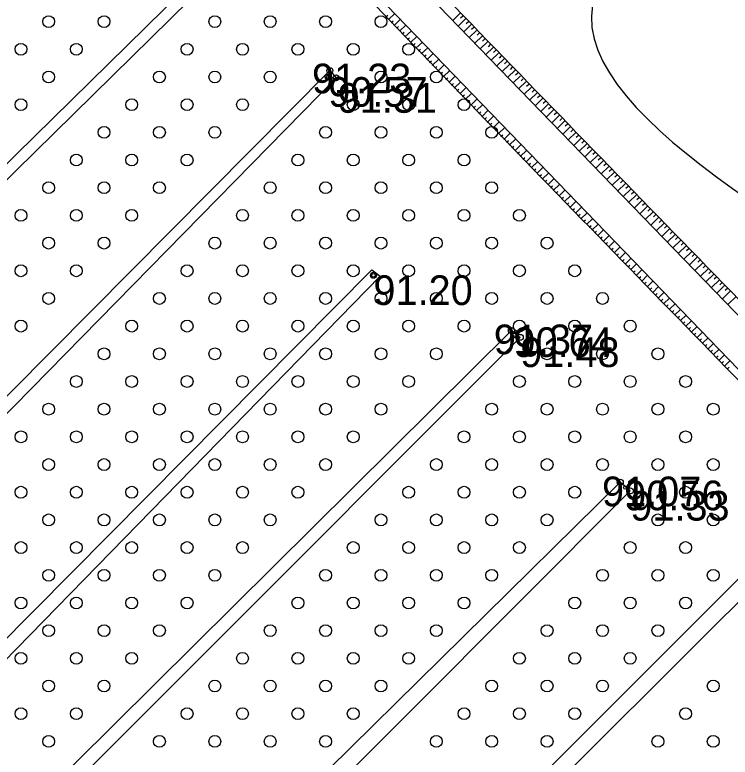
# Model space of a CAD drawing. Extents: x 316000 to 728450, y 314368 to 726000.
# Drawn here: x 725766.2 to 725856.6, y 315456.5 to 315550.4 of the extents above; entities that cross this region are included whole.
import ezdxf

# ---------------------------------------------------------------- set-up
doc = ezdxf.new("R2010")
doc.units = 0
for name, color, linetype in [('HIDG_ELEM_####_####_#', 7, 'Continuous'), ('HIDG_GRAV_####_####_#', 7, 'Continuous'), ('RELJ_AATZ_####_TKST_#', 7, 'Continuous'), ('RELJ_ELEM_####_####_#', 7, 'Continuous'), ('RELJ_HORZ_PAMT_####_#', 7, 'Continuous'), ('RELJ_NOGA_####_####_#', 7, 'Continuous'), ('TERT_ELEM_####_####_#', 7, 'Continuous')]:
    doc.layers.add(name, color=color, linetype=linetype)

msp = doc.modelspace()

# ---------------------------------------------------------------- linework, layer by layer
at = {"layer": 'HIDG_ELEM_####_####_#'}
for centre in [(725805.842, 315542.486), (725811.549, 315517.418), (725829.423, 315509.915), (725843.383, 315490.595)]:
    msp.add_circle(centre, 0.225, dxfattribs=at)
at = {"layer": 'HIDG_GRAV_####_####_#'}
for points in [[(726259.175, 315086.515), (726260.768, 315088.859), (726179.005, 315175.766), (726127.859, 315229.056), (726063.055, 315296.073), (725998.338, 315364.317), (725936.648, 315430.32), (725875.345, 315494.083), (725809.436, 315562.192), (725743.944, 315631.872)], [(725741.161, 315628.109), (725806.062, 315558.993), (725870.895, 315491.871), (725934.12, 315427.077), (725995.775, 315361.632), (726059.846, 315293.396), (726126.03, 315226.728), (726194.491, 315154.86), (726259.175, 315086.515)], [(725789.821, 315555.772), (725790.78, 315554.709), (725668.395, 315434.39), (725667.719, 315435.797), (725789.821, 315555.772)], [(725806.049, 315543.31), (725806.834, 315542.392), (725671.92, 315404.847), (725670.303, 315406.432), (725806.049, 315543.31)], [(725811.357, 315518.129), (725812.41, 315517.334), (725689.872, 315391.756), (725687.944, 315393.638), (725811.357, 315518.129)], [(725828.984, 315510.455), (725830.109, 315509.579), (725700.226, 315379.564), (725698.486, 315381.013), (725828.984, 315510.455)], [(725715.114, 315365.54), (725717.512, 315363.33), (725844.018, 315490.166), (725842.748, 315491.255), (725715.114, 315365.54)], [(725860.372, 315481.728), (725862.243, 315480.659), (725694.367, 315313.346), (725693.183, 315314.534), (725860.372, 315481.728)]]:
    msp.add_lwpolyline(points, dxfattribs=at)
at = {"layer": 'RELJ_ELEM_####_####_#'}
for centre in [(725806.049, 315543.31), (725805.842, 315542.486), (725806.834, 315542.392), (725811.549, 315517.418), (725828.984, 315510.455), (725829.423, 315509.915), (725830.109, 315509.579), (725842.748, 315491.255), (725844.018, 315490.166)]:
    msp.add_circle(centre, 0.375, dxfattribs=at)
at = {"layer": 'RELJ_HORZ_PAMT_####_#'}
msp.add_spline([(726116.344, 315699.088), (726105.94, 315702.687), (726040.128, 315715), (725990.823, 315710.424), (725942.032, 315708.248), (725920.28, 315706.773), (725880.366, 315714.514), (725859.054, 315708.681), (725859.054, 315672.662), (725851.263, 315613.969), (725853.471, 315568.895), (725840.997, 315555.788), (725885.558, 315509.629), (725935.943, 315461.491), (725983.423, 315406.25), (726032.861, 315360.511), (726082.852, 315311.191), (726122.235, 315248.757), (726137.049, 315229.286), (726180.187, 315183.1), (726194.517, 315168.27), (726211.91, 315146.926), (726212.513, 315143.157)], degree=3, dxfattribs=at)
at = {"layer": 'RELJ_NOGA_####_####_#'}
for p, q in [((725813.115, 315550.109), (725813.354, 315550.336)), ((725813.46, 315549.747), (725814.258, 315550.507)), ((725814.149, 315549.023), (725814.953, 315549.789)), ((725822.506, 315550.56), (725821.566, 315549.657)), ((725823.199, 315549.839), (725822.262, 315548.938)), ((725822.852, 315550.199), (725822.571, 315549.929)), ((725813.804, 315549.385), (725814.045, 315549.614)), ((725814.494, 315548.661), (725814.736, 315548.891)), ((725814.839, 315548.299), (725815.647, 315549.069)), ((725823.892, 315549.118), (725822.958, 315548.219)), ((725823.545, 315549.479), (725823.265, 315549.209)), ((725815.184, 315547.937), (725815.427, 315548.169)), ((725815.53, 315547.575), (725816.342, 315548.351)), ((725824.586, 315548.398), (725823.654, 315547.5)), ((725824.239, 315548.758), (725823.959, 315548.488)), ((725824.933, 315548.038), (725824.653, 315547.769)), ((725815.875, 315547.214), (725816.119, 315547.447)), ((725816.22, 315546.852), (725817.036, 315547.632)), ((725816.912, 315546.13), (725817.73, 315546.913)), ((725825.279, 315547.678), (725824.349, 315546.781)), ((725825.974, 315546.958), (725825.045, 315546.062)), ((725825.627, 315547.318), (725825.348, 315547.049)), ((725816.566, 315546.491), (725816.811, 315546.725)), ((725817.257, 315545.768), (725817.503, 315546.004)), ((725817.603, 315545.407), (725818.424, 315546.194)), ((725826.668, 315546.238), (725825.741, 315545.343)), ((725826.321, 315546.598), (725826.042, 315546.329)), ((725817.949, 315545.046), (725818.196, 315545.283)), ((725818.295, 315544.685), (725819.119, 315545.475)), ((725827.363, 315545.519), (725826.436, 315544.624)), ((725827.015, 315545.878), (725826.737, 315545.61)), ((725827.71, 315545.159), (725827.432, 315544.891)), ((725818.641, 315544.324), (725818.888, 315544.562)), ((725818.987, 315543.963), (725819.813, 315544.756)), ((725828.058, 315544.8), (725827.132, 315543.905)), ((725828.405, 315544.44), (725828.127, 315544.172)), ((725819.333, 315543.603), (725819.581, 315543.841)), ((725819.679, 315543.242), (725820.508, 315544.037)), ((725820.372, 315542.521), (725821.202, 315543.318)), ((725828.753, 315544.081), (725827.828, 315543.186)), ((725829.448, 315543.362), (725828.523, 315542.467)), ((725829.1, 315543.722), (725828.823, 315543.453)), ((725820.026, 315542.881), (725820.274, 315543.12)), ((725820.719, 315542.16), (725820.968, 315542.4)), ((725821.065, 315541.8), (725821.897, 315542.599)), ((725830.144, 315542.644), (725829.219, 315541.748)), ((725829.796, 315543.003), (725829.519, 315542.734)), ((725830.492, 315542.285), (725830.214, 315542.016)), ((725821.412, 315541.44), (725821.661, 315541.68)), ((725821.759, 315541.079), (725822.591, 315541.881)), ((725830.84, 315541.926), (725829.915, 315541.03)), ((725831.188, 315541.567), (725830.91, 315541.298)), ((725822.105, 315540.719), (725822.355, 315540.96)), ((725822.452, 315540.359), (725823.285, 315541.162)), ((725823.146, 315539.639), (725823.98, 315540.443)), ((725831.536, 315541.208), (725830.611, 315540.311)), ((725832.232, 315540.49), (725831.306, 315539.592)), ((725831.884, 315540.849), (725831.606, 315540.58)), ((725822.799, 315539.999), (725823.049, 315540.24)), ((725823.493, 315539.279), (725823.743, 315539.52)), ((725823.84, 315538.919), (725824.674, 315539.724)), ((725832.928, 315539.772), (725832.002, 315538.873)), ((725832.58, 315540.131), (725832.302, 315539.861)), ((725833.277, 315539.414), (725832.999, 315539.144)), ((725824.188, 315538.56), (725824.438, 315538.801)), ((725824.535, 315538.2), (725825.369, 315539.005)), ((725833.625, 315539.055), (725832.697, 315538.154)), ((725833.974, 315538.696), (725833.695, 315538.426)), ((725824.882, 315537.84), (725825.132, 315538.082)), ((725825.23, 315537.48), (725826.063, 315538.286)), ((725825.925, 315536.761), (725826.758, 315537.567)), ((725834.322, 315538.338), (725833.393, 315537.435)), ((725835.019, 315537.621), (725834.089, 315536.716)), ((725834.671, 315537.979), (725834.392, 315537.708)), ((725825.577, 315537.121), (725825.827, 315537.363)), ((725826.272, 315536.402), (725826.522, 315536.644)), ((725826.62, 315536.043), (725827.452, 315536.848)), ((725835.716, 315536.904), (725834.785, 315535.997)), ((725835.368, 315537.262), (725835.088, 315536.991)), ((725826.968, 315535.683), (725827.217, 315535.925)), ((725827.315, 315535.324), (725828.147, 315536.129)), ((725836.414, 315536.187), (725835.48, 315535.279)), ((725836.065, 315536.546), (725835.785, 315536.273)), ((725836.763, 315535.829), (725836.482, 315535.556)), ((725827.663, 315534.965), (725827.912, 315535.206)), ((725828.011, 315534.606), (725828.841, 315535.41)), ((725837.111, 315535.471), (725836.175, 315534.56)), ((725837.809, 315534.755), (725836.871, 315533.841)), ((725837.46, 315535.113), (725837.179, 315534.839)), ((725828.359, 315534.247), (725828.608, 315534.488)), ((725828.707, 315533.888), (725829.535, 315534.691)), ((725829.055, 315533.529), (725829.303, 315533.769)), ((725829.403, 315533.17), (725830.23, 315533.972)), ((725838.507, 315534.038), (725837.567, 315533.122)), ((725838.158, 315534.396), (725837.876, 315534.122)), ((725829.751, 315532.811), (725829.999, 315533.051)), ((725830.099, 315532.452), (725830.925, 315533.253)), ((725839.205, 315533.322), (725838.263, 315532.403)), ((725838.856, 315533.68), (725838.574, 315533.405)), ((725839.554, 315532.964), (725839.271, 315532.688)), ((725830.448, 315532.093), (725830.695, 315532.333)), ((725830.796, 315531.735), (725831.619, 315532.534)), ((725839.903, 315532.606), (725838.958, 315531.684)), ((725840.601, 315531.89), (725839.653, 315530.966)), ((725840.252, 315532.248), (725839.968, 315531.971)), ((725831.144, 315531.376), (725831.391, 315531.615)), ((725831.493, 315531.017), (725832.314, 315531.815)), ((725832.19, 315530.3), (725833.008, 315531.096)), ((725841.3, 315531.175), (725840.349, 315530.247)), ((725840.951, 315531.533), (725840.666, 315531.255)), ((725831.841, 315530.659), (725832.087, 315530.898)), ((725832.538, 315529.942), (725832.783, 315530.18)), ((725832.887, 315529.583), (725833.703, 315530.376)), ((725841.998, 315530.459), (725841.045, 315529.528)), ((725841.649, 315530.817), (725841.364, 315530.538)), ((725842.348, 315530.101), (725842.061, 315529.822)), ((725833.235, 315529.225), (725833.48, 315529.462)), ((725833.584, 315528.866), (725834.397, 315529.657)), ((725842.697, 315529.744), (725841.74, 315528.81)), ((725843.046, 315529.386), (725842.759, 315529.105)), ((725833.933, 315528.508), (725834.176, 315528.745)), ((725834.282, 315528.15), (725835.092, 315528.938)), ((725834.979, 315527.433), (725835.786, 315528.219)), ((725843.396, 315529.028), (725842.436, 315528.091)), ((725844.095, 315528.313), (725843.131, 315527.372)), ((725843.745, 315528.671), (725843.457, 315528.389)), ((725834.63, 315527.791), (725834.873, 315528.028)), ((725835.328, 315527.075), (725835.57, 315527.31)), ((725835.677, 315526.717), (725836.481, 315527.5)), ((725844.793, 315527.598), (725843.827, 315526.653)), ((725844.444, 315527.955), (725844.155, 315527.673)), ((725845.143, 315527.24), (725844.852, 315526.956)), ((725836.026, 315526.359), (725836.267, 315526.593)), ((725836.375, 315526.001), (725837.175, 315526.781)), ((725845.492, 315526.883), (725844.522, 315525.934)), ((725845.842, 315526.525), (725845.55, 315526.24)), ((725836.724, 315525.643), (725836.963, 315525.876)), ((725837.073, 315525.285), (725837.87, 315526.062)), ((725837.771, 315524.569), (725838.565, 315525.343)), ((725846.191, 315526.168), (725845.218, 315525.216)), ((725846.89, 315525.452), (725845.913, 315524.497)), ((725846.541, 315525.81), (725846.248, 315525.524)), ((725837.422, 315524.927), (725837.66, 315525.159)), ((725838.12, 315524.211), (725838.358, 315524.443)), ((725838.469, 315523.853), (725839.259, 315524.624)), ((725847.59, 315524.737), (725846.609, 315523.778)), ((725847.24, 315525.095), (725846.946, 315524.808)), ((725847.939, 315524.38), (725847.644, 315524.092)), ((725838.819, 315523.495), (725839.055, 315523.726)), ((725839.168, 315523.137), (725839.954, 315523.904)), ((725848.289, 315524.023), (725847.304, 315523.06)), ((725848.638, 315523.665), (725848.342, 315523.376)), ((725839.517, 315522.779), (725839.752, 315523.009)), ((725839.866, 315522.422), (725840.648, 315523.185)), ((725848.988, 315523.308), (725848, 315522.341)), ((725849.687, 315522.593), (725848.695, 315521.622)), ((725849.338, 315522.95), (725849.041, 315522.66)), ((725840.216, 315522.064), (725840.45, 315522.292)), ((725840.565, 315521.706), (725841.343, 315522.466)), ((725840.914, 315521.348), (725841.147, 315521.576)), ((725841.264, 315520.991), (725842.038, 315521.747)), ((725850.386, 315521.878), (725849.391, 315520.904)), ((725850.037, 315522.235), (725849.739, 315521.944)), ((725841.613, 315520.633), (725841.845, 315520.859)), ((725841.962, 315520.275), (725842.732, 315521.028)), ((725851.086, 315521.163), (725850.086, 315520.185)), ((725850.736, 315521.52), (725850.437, 315521.228)), ((725851.435, 315520.805), (725851.135, 315520.512)), ((725842.312, 315519.918), (725842.542, 315520.143)), ((725842.661, 315519.56), (725843.427, 315520.309)), ((725851.785, 315520.448), (725850.781, 315519.466)), ((725852.484, 315519.733), (725851.477, 315518.748)), ((725852.135, 315520.091), (725851.833, 315519.796)), ((725843.011, 315519.203), (725843.24, 315519.426)), ((725843.36, 315518.845), (725844.122, 315519.59)), ((725844.059, 315518.13), (725844.816, 315518.87)), ((725853.184, 315519.018), (725852.172, 315518.029)), ((725852.834, 315519.376), (725852.531, 315519.08)), ((725843.71, 315518.487), (725843.937, 315518.71)), ((725844.409, 315517.772), (725844.635, 315517.994)), ((725844.758, 315517.415), (725845.511, 315518.151)), ((725853.883, 315518.303), (725852.868, 315517.311)), ((725853.533, 315518.661), (725853.229, 315518.364)), ((725854.232, 315517.946), (725853.927, 315517.648)), ((725845.108, 315517.057), (725845.333, 315517.278)), ((725845.457, 315516.7), (725846.206, 315517.432)), ((725854.582, 315517.589), (725853.563, 315516.592)), ((725855.281, 315516.874), (725854.259, 315515.873)), ((725854.932, 315517.231), (725854.625, 315516.932)), ((725845.807, 315516.342), (725846.031, 315516.561)), ((725846.156, 315515.985), (725846.901, 315516.712)), ((725846.856, 315515.27), (725847.595, 315515.993)), ((725855.98, 315516.159), (725854.954, 315515.155)), ((725855.631, 315516.516), (725855.323, 315516.216)), ((725846.506, 315515.627), (725846.729, 315515.845)), ((725847.205, 315514.912), (725847.426, 315515.129)), ((725847.555, 315514.555), (725848.29, 315515.274)), ((725856.679, 315515.444), (725855.649, 315514.436)), ((725856.33, 315515.801), (725856.021, 315515.5)), ((725847.904, 315514.197), (725848.124, 315514.412)), ((725848.254, 315513.84), (725848.985, 315514.555)), ((725857.379, 315514.729), (725856.345, 315513.718)), ((725848.604, 315513.482), (725848.822, 315513.696)), ((725848.953, 315513.125), (725849.68, 315513.835)), ((725849.303, 315512.768), (725849.52, 315512.98)), ((725849.652, 315512.41), (725850.374, 315513.116)), ((725850.002, 315512.053), (725850.218, 315512.264)), ((725850.352, 315511.695), (725851.069, 315512.397)), ((725850.701, 315511.338), (725850.916, 315511.548)), ((725851.051, 315510.98), (725851.764, 315511.678)), ((725851.4, 315510.623), (725851.614, 315510.831)), ((725851.75, 315510.265), (725852.459, 315510.958)), ((725852.1, 315509.908), (725852.312, 315510.115)), ((725852.449, 315509.55), (725853.153, 315510.239)), ((725852.799, 315509.193), (725853.009, 315509.399)), ((725853.148, 315508.835), (725853.848, 315509.52)), ((725853.498, 315508.478), (725853.707, 315508.683)), ((725853.847, 315508.12), (725854.543, 315508.8)), ((725854.197, 315507.763), (725854.405, 315507.966)), ((725854.547, 315507.405), (725855.238, 315508.081)), ((725854.896, 315507.048), (725855.103, 315507.25)), ((725855.245, 315506.69), (725855.933, 315507.362)), ((725855.944, 315505.975), (725856.627, 315506.642)), ((725855.595, 315506.333), (725855.8, 315506.533)), ((725856.294, 315505.617), (725856.498, 315505.817))]:
    msp.add_line(p, q, dxfattribs=at)
for points in [[(726259.118, 315084.507), (726262.723, 315089.259), (726261.561, 315090.837), (726260.205, 315092.42), (726257.293, 315095.532), (726218.912, 315136.383), (726180.307, 315176.838), (726128.672, 315229.97), (726063.701, 315298.11), (725999.895, 315366.094), (725937.206, 315432.091), (725876.347, 315495.232), (725810.578, 315563.083), (725744.701, 315632.911)], [(725740.862, 315626.984), (725805.544, 315558.116), (725870.385, 315491.147), (725932.803, 315426.796), (725994.977, 315360.836), (726059.661, 315292.118), (726075.746, 315275.458), (726092.085, 315259.043), (726108.47, 315242.673), (726124.693, 315226.144), (726193.269, 315154.025), (726250.062, 315092.6), (726256.318, 315085.83), (726258.824, 315084.289), (726259.118, 315084.507)]]:
    msp.add_spline(points, degree=3, dxfattribs=at)
at = {"layer": 'TERT_ELEM_####_####_#'}
for centre in [(725770.5, 315549.5), (725777.5, 315549.5), (725791.5, 315549.5), (725798.5, 315549.5), (725805.5, 315549.5), (725812.5, 315549.5), (725767, 315546), (725774, 315546), (725788, 315546), (725795, 315546), (725802, 315546), (725809, 315546), (725816, 315546), (725770.5, 315542.5), (725784.5, 315542.5), (725791.5, 315542.5), (725798.5, 315542.5), (725812.5, 315542.5), (725819.5, 315542.5), (725767, 315539), (725781, 315539), (725788, 315539), (725795, 315539), (725809, 315539), (725816, 315539), (725823, 315539), (725777.5, 315535.5), (725784.5, 315535.5), (725791.5, 315535.5), (725805.5, 315535.5), (725812.5, 315535.5), (725819.5, 315535.5), (725826.5, 315535.5), (725774, 315532), (725781, 315532), (725788, 315532), (725802, 315532), (725809, 315532), (725816, 315532), (725823, 315532), (725770.5, 315528.5), (725777.5, 315528.5), (725784.5, 315528.5), (725798.5, 315528.5), (725805.5, 315528.5), (725812.5, 315528.5), (725819.5, 315528.5), (725826.5, 315528.5), (725767, 315525), (725774, 315525), (725781, 315525), (725795, 315525), (725802, 315525), (725809, 315525), (725816, 315525), (725823, 315525), (725830, 315525), (725770.5, 315521.5), (725777.5, 315521.5), (725791.5, 315521.5), (725798.5, 315521.5), (725805.5, 315521.5), (725812.5, 315521.5), (725819.5, 315521.5), (725826.5, 315521.5), (725833.5, 315521.5), (725767, 315518), (725774, 315518), (725788, 315518), (725795, 315518), (725802, 315518), (725809, 315518), (725816, 315518), (725823, 315518), (725830, 315518), (725837, 315518), (725770.5, 315514.5), (725784.5, 315514.5), (725791.5, 315514.5), (725798.5, 315514.5), (725805.5, 315514.5), (725812.5, 315514.5), (725819.5, 315514.5), (725826.5, 315514.5), (725833.5, 315514.5), (725840.5, 315514.5), (725767, 315511), (725781, 315511), (725788, 315511), (725795, 315511), (725802, 315511), (725809, 315511), (725816, 315511), (725823, 315511), (725830, 315511), (725837, 315511), (725844, 315511), (725777.5, 315507.5), (725784.5, 315507.5), (725791.5, 315507.5), (725798.5, 315507.5), (725805.5, 315507.5), (725812.5, 315507.5), (725819.5, 315507.5), (725833.5, 315507.5), (725840.5, 315507.5), (725847.5, 315507.5), (725774, 315504), (725781, 315504), (725788, 315504), (725795, 315504), (725802, 315504), (725809, 315504), (725816, 315504), (725830, 315504), (725837, 315504), (725844, 315504), (725851, 315504), (725770.5, 315500.5), (725777.5, 315500.5), (725784.5, 315500.5), (725791.5, 315500.5), (725798.5, 315500.5), (725805.5, 315500.5), (725812.5, 315500.5), (725826.5, 315500.5), (725833.5, 315500.5), (725840.5, 315500.5), (725847.5, 315500.5), (725854.5, 315500.5), (725767, 315497), (725774, 315497), (725781, 315497), (725788, 315497), (725795, 315497), (725802, 315497), (725809, 315497), (725823, 315497), (725830, 315497), (725837, 315497), (725844, 315497), (725851, 315497), (725770.5, 315493.5), (725777.5, 315493.5), (725784.5, 315493.5), (725791.5, 315493.5), (725798.5, 315493.5), (725805.5, 315493.5), (725819.5, 315493.5), (725826.5, 315493.5), (725833.5, 315493.5), (725840.5, 315493.5), (725847.5, 315493.5), (725854.5, 315493.5), (725767, 315490), (725774, 315490), (725781, 315490), (725788, 315490), (725795, 315490), (725802, 315490), (725816, 315490), (725823, 315490), (725830, 315490), (725837, 315490), (725851, 315490), (725770.5, 315486.5), (725777.5, 315486.5), (725784.5, 315486.5), (725791.5, 315486.5), (725798.5, 315486.5), (725812.5, 315486.5), (725819.5, 315486.5), (725826.5, 315486.5), (725833.5, 315486.5), (725847.5, 315486.5), (725854.5, 315486.5), (725767, 315483), (725774, 315483), (725781, 315483), (725788, 315483), (725795, 315483), (725809, 315483), (725816, 315483), (725823, 315483), (725830, 315483), (725844, 315483), (725851, 315483), (725770.5, 315479.5), (725777.5, 315479.5), (725784.5, 315479.5), (725791.5, 315479.5), (725805.5, 315479.5), (725812.5, 315479.5), (725819.5, 315479.5), (725826.5, 315479.5), (725840.5, 315479.5), (725847.5, 315479.5), (725854.5, 315479.5), (725767, 315476), (725774, 315476), (725781, 315476), (725788, 315476), (725802, 315476), (725809, 315476), (725816, 315476), (725823, 315476), (725837, 315476), (725844, 315476), (725851, 315476), (725770.5, 315472.5), (725777.5, 315472.5), (725784.5, 315472.5), (725798.5, 315472.5), (725805.5, 315472.5), (725812.5, 315472.5), (725819.5, 315472.5), (725833.5, 315472.5), (725840.5, 315472.5), (725847.5, 315472.5), (725767, 315469), (725774, 315469), (725781, 315469), (725795, 315469), (725802, 315469), (725809, 315469), (725816, 315469), (725830, 315469), (725837, 315469), (725844, 315469), (725770.5, 315465.5), (725777.5, 315465.5), (725791.5, 315465.5), (725798.5, 315465.5), (725805.5, 315465.5), (725812.5, 315465.5), (725826.5, 315465.5), (725833.5, 315465.5), (725840.5, 315465.5), (725854.5, 315465.5), (725767, 315462), (725774, 315462), (725788, 315462), (725795, 315462), (725802, 315462), (725809, 315462), (725823, 315462), (725830, 315462), (725837, 315462), (725851, 315462), (725770.5, 315458.5), (725784.5, 315458.5), (725791.5, 315458.5), (725798.5, 315458.5), (725805.5, 315458.5), (725819.5, 315458.5), (725826.5, 315458.5), (725833.5, 315458.5), (725847.5, 315458.5), (725854.5, 315458.5)]:
    msp.add_circle(centre, 0.75, dxfattribs=at)

# ---------------------------------------------------------------- texts
at = {"layer": 'RELJ_AATZ_####_TKST_#'}
for s, p in [('91.23', (725803.788, 315540.434)), ('90.57', (725805.842, 315538.736)), ('91.31', (725807.035, 315537.976)), ('91.20', (725811.549, 315513.668)), ('91.37', (725826.761, 315507.447)), ('90.64', (725829.248, 315507.096)), ('91.48', (725830.109, 315505.829)), ('91.07', (725840.438, 315488.229)), ('90.56', (725843.237, 315487.717)), ('91.33', (725844.018, 315486.416))]:
    msp.add_text(s, height=3.75, dxfattribs=at).set_placement(p)

doc.saveas('drawing.dxf')
